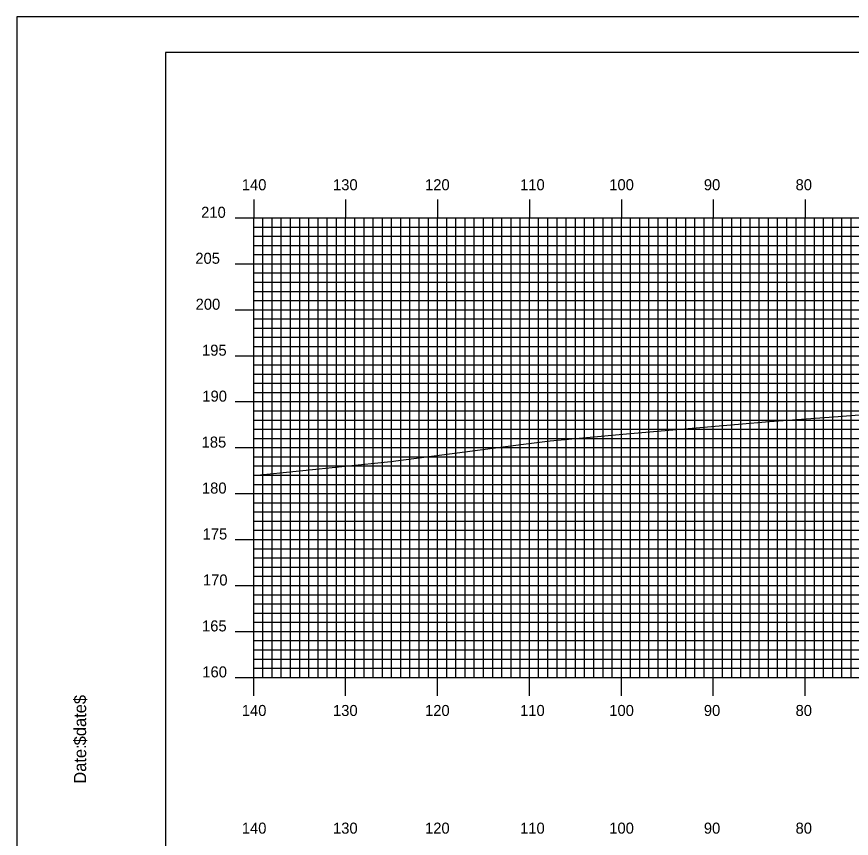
# Model space of a CAD drawing. Extents: x 1794453 to 1794796, y 442591 to 442811.
# Drawn here: x 1794452.6 to 1794543.4, y 442721.2 to 442810.5 of the extents above; entities that cross this region are included whole.
import ezdxf

# ---------------------------------------------------------------- set-up
doc = ezdxf.new("R2010")
doc.units = 0
for name, color, linetype in [('BORDER', 7, 'Continuous'), ('H_V ANNOTATION', 7, 'Continuous'), ('MAJOR', 7, 'Continuous'), ('MINOR', 7, 'Continuous'), ('PLOT BOUNDARY', 7, 'Continuous'), ('S_Roadway_Centerline', 7, 'Continuous')]:
    doc.layers.add(name, color=color, linetype=linetype)

msp = doc.modelspace()

# ---------------------------------------------------------------- linework, layer by layer
at = {"layer": 'BORDER'}
msp.add_lwpolyline([(1794468.74, 442596.665), (1794788.74, 442596.665), (1794788.74, 442806.665), (1794468.74, 442806.665)], close=True, dxfattribs=at)
at = {"layer": 'MAJOR'}
for p, q in [((1794478.34, 442790.669), (1794478.34, 442788.665)), ((1794488.34, 442790.669), (1794488.34, 442788.665)), ((1794498.34, 442790.669), (1794498.34, 442788.665)), ((1794508.34, 442790.669), (1794508.34, 442788.665)), ((1794518.34, 442790.669), (1794518.34, 442788.665)), ((1794528.34, 442790.669), (1794528.34, 442788.665)), ((1794538.34, 442790.669), (1794538.34, 442788.665)), ((1794476.336, 442788.665), (1794478.34, 442788.665)), ((1794478.34, 442788.665), (1794758.34, 442788.665)), ((1794478.34, 442738.665), (1794478.34, 442788.665)), ((1794478.34, 442738.665), (1794478.34, 442788.665)), ((1794478.34, 442788.665), (1794758.34, 442788.665)), ((1794488.34, 442738.665), (1794488.34, 442788.665)), ((1794498.34, 442738.665), (1794498.34, 442788.665)), ((1794508.34, 442738.665), (1794508.34, 442788.665)), ((1794518.34, 442738.665), (1794518.34, 442788.665)), ((1794528.34, 442738.665), (1794528.34, 442788.665)), ((1794538.34, 442738.665), (1794538.34, 442788.665)), ((1794476.336, 442783.665), (1794478.34, 442783.665)), ((1794478.34, 442783.665), (1794758.34, 442783.665)), ((1794476.336, 442778.665), (1794478.34, 442778.665)), ((1794478.34, 442778.665), (1794758.34, 442778.665)), ((1794476.336, 442773.665), (1794478.34, 442773.665)), ((1794478.34, 442773.665), (1794758.34, 442773.665)), ((1794476.336, 442768.665), (1794478.34, 442768.665)), ((1794478.34, 442768.665), (1794758.34, 442768.665)), ((1794476.336, 442763.665), (1794478.34, 442763.665)), ((1794478.34, 442763.665), (1794758.34, 442763.665)), ((1794476.336, 442758.665), (1794478.34, 442758.665)), ((1794478.34, 442758.665), (1794758.34, 442758.665)), ((1794476.336, 442753.665), (1794478.34, 442753.665)), ((1794478.34, 442753.665), (1794758.34, 442753.665)), ((1794476.336, 442748.665), (1794478.34, 442748.665)), ((1794478.34, 442748.665), (1794758.34, 442748.665)), ((1794476.336, 442743.665), (1794478.34, 442743.665)), ((1794478.34, 442743.665), (1794758.34, 442743.665)), ((1794476.336, 442738.665), (1794478.34, 442738.665)), ((1794478.34, 442738.665), (1794758.34, 442738.665)), ((1794478.34, 442738.665), (1794758.34, 442738.665)), ((1794478.34, 442736.661), (1794478.34, 442738.665)), ((1794488.34, 442736.661), (1794488.34, 442738.665)), ((1794498.34, 442736.661), (1794498.34, 442738.665)), ((1794508.34, 442736.661), (1794508.34, 442738.665)), ((1794518.34, 442736.661), (1794518.34, 442738.665)), ((1794528.34, 442736.661), (1794528.34, 442738.665)), ((1794538.34, 442736.661), (1794538.34, 442738.665))]:
    msp.add_line(p, q, dxfattribs=at)
at = {"layer": 'MINOR'}
for p, q in [((1794479.34, 442738.665), (1794479.34, 442788.665)), ((1794480.34, 442738.665), (1794480.34, 442788.665)), ((1794481.34, 442738.665), (1794481.34, 442788.665)), ((1794482.34, 442738.665), (1794482.34, 442788.665)), ((1794483.34, 442738.665), (1794483.34, 442788.665)), ((1794484.34, 442738.665), (1794484.34, 442788.665)), ((1794485.34, 442738.665), (1794485.34, 442788.665)), ((1794486.34, 442738.665), (1794486.34, 442788.665)), ((1794487.34, 442738.665), (1794487.34, 442788.665)), ((1794489.34, 442738.665), (1794489.34, 442788.665)), ((1794490.34, 442738.665), (1794490.34, 442788.665)), ((1794491.34, 442738.665), (1794491.34, 442788.665)), ((1794492.34, 442738.665), (1794492.34, 442788.665)), ((1794493.34, 442738.665), (1794493.34, 442788.665)), ((1794494.34, 442738.665), (1794494.34, 442788.665)), ((1794495.34, 442738.665), (1794495.34, 442788.665)), ((1794496.34, 442738.665), (1794496.34, 442788.665)), ((1794497.34, 442738.665), (1794497.34, 442788.665)), ((1794499.34, 442738.665), (1794499.34, 442788.665)), ((1794500.34, 442738.665), (1794500.34, 442788.665)), ((1794501.34, 442738.665), (1794501.34, 442788.665)), ((1794502.34, 442738.665), (1794502.34, 442788.665)), ((1794503.34, 442738.665), (1794503.34, 442788.665)), ((1794504.34, 442738.665), (1794504.34, 442788.665)), ((1794505.34, 442738.665), (1794505.34, 442788.665)), ((1794506.34, 442738.665), (1794506.34, 442788.665)), ((1794507.34, 442738.665), (1794507.34, 442788.665)), ((1794509.34, 442738.665), (1794509.34, 442788.665)), ((1794510.34, 442738.665), (1794510.34, 442788.665)), ((1794511.34, 442738.665), (1794511.34, 442788.665)), ((1794512.34, 442738.665), (1794512.34, 442788.665)), ((1794513.34, 442738.665), (1794513.34, 442788.665)), ((1794514.34, 442738.665), (1794514.34, 442788.665)), ((1794515.34, 442738.665), (1794515.34, 442788.665)), ((1794516.34, 442738.665), (1794516.34, 442788.665)), ((1794517.34, 442738.665), (1794517.34, 442788.665)), ((1794519.34, 442738.665), (1794519.34, 442788.665)), ((1794520.34, 442738.665), (1794520.34, 442788.665)), ((1794521.34, 442738.665), (1794521.34, 442788.665)), ((1794522.34, 442738.665), (1794522.34, 442788.665)), ((1794523.34, 442738.665), (1794523.34, 442788.665)), ((1794524.34, 442738.665), (1794524.34, 442788.665)), ((1794525.34, 442738.665), (1794525.34, 442788.665)), ((1794526.34, 442738.665), (1794526.34, 442788.665)), ((1794527.34, 442738.665), (1794527.34, 442788.665)), ((1794529.34, 442738.665), (1794529.34, 442788.665)), ((1794530.34, 442738.665), (1794530.34, 442788.665)), ((1794531.34, 442738.665), (1794531.34, 442788.665)), ((1794532.34, 442738.665), (1794532.34, 442788.665)), ((1794533.34, 442738.665), (1794533.34, 442788.665)), ((1794534.34, 442738.665), (1794534.34, 442788.665)), ((1794535.34, 442738.665), (1794535.34, 442788.665)), ((1794536.34, 442738.665), (1794536.34, 442788.665)), ((1794537.34, 442738.665), (1794537.34, 442788.665)), ((1794539.34, 442738.665), (1794539.34, 442788.665)), ((1794540.34, 442738.665), (1794540.34, 442788.665)), ((1794541.34, 442738.665), (1794541.34, 442788.665)), ((1794542.34, 442738.665), (1794542.34, 442788.665)), ((1794543.34, 442738.665), (1794543.34, 442788.665)), ((1794478.34, 442787.665), (1794758.34, 442787.665)), ((1794478.34, 442787.665), (1794480.344, 442787.665)), ((1794478.34, 442786.665), (1794758.34, 442786.665)), ((1794478.34, 442786.665), (1794480.344, 442786.665)), ((1794478.34, 442785.665), (1794758.34, 442785.665)), ((1794478.34, 442785.665), (1794480.344, 442785.665)), ((1794478.34, 442784.665), (1794758.34, 442784.665)), ((1794478.34, 442784.665), (1794480.344, 442784.665)), ((1794478.34, 442782.665), (1794758.34, 442782.665)), ((1794478.34, 442782.665), (1794480.344, 442782.665)), ((1794478.34, 442781.665), (1794758.34, 442781.665)), ((1794478.34, 442781.665), (1794480.344, 442781.665)), ((1794478.34, 442780.665), (1794758.34, 442780.665)), ((1794478.34, 442780.665), (1794480.344, 442780.665)), ((1794478.34, 442779.665), (1794758.34, 442779.665)), ((1794478.34, 442779.665), (1794480.344, 442779.665)), ((1794478.34, 442777.665), (1794758.34, 442777.665)), ((1794478.34, 442777.665), (1794480.344, 442777.665)), ((1794478.34, 442776.665), (1794758.34, 442776.665)), ((1794478.34, 442776.665), (1794480.344, 442776.665)), ((1794478.34, 442775.665), (1794758.34, 442775.665)), ((1794478.34, 442775.665), (1794480.344, 442775.665)), ((1794478.34, 442774.665), (1794758.34, 442774.665)), ((1794478.34, 442774.665), (1794480.344, 442774.665)), ((1794478.34, 442772.665), (1794758.34, 442772.665)), ((1794478.34, 442772.665), (1794480.344, 442772.665)), ((1794478.34, 442771.665), (1794758.34, 442771.665)), ((1794478.34, 442771.665), (1794480.344, 442771.665)), ((1794478.34, 442770.665), (1794758.34, 442770.665)), ((1794478.34, 442770.665), (1794480.344, 442770.665)), ((1794478.34, 442769.665), (1794758.34, 442769.665)), ((1794478.34, 442769.665), (1794480.344, 442769.665)), ((1794478.34, 442767.665), (1794758.34, 442767.665)), ((1794478.34, 442767.665), (1794480.344, 442767.665)), ((1794478.34, 442766.665), (1794758.34, 442766.665)), ((1794478.34, 442766.665), (1794480.344, 442766.665)), ((1794478.34, 442765.665), (1794758.34, 442765.665)), ((1794478.34, 442765.665), (1794480.344, 442765.665)), ((1794478.34, 442764.665), (1794758.34, 442764.665)), ((1794478.34, 442764.665), (1794480.344, 442764.665)), ((1794478.34, 442762.665), (1794758.34, 442762.665)), ((1794478.34, 442762.665), (1794480.344, 442762.665)), ((1794478.34, 442761.665), (1794758.34, 442761.665)), ((1794478.34, 442761.665), (1794480.344, 442761.665)), ((1794478.34, 442760.665), (1794758.34, 442760.665)), ((1794478.34, 442760.665), (1794480.344, 442760.665)), ((1794478.34, 442759.665), (1794758.34, 442759.665)), ((1794478.34, 442759.665), (1794480.344, 442759.665)), ((1794478.34, 442757.665), (1794758.34, 442757.665)), ((1794478.34, 442757.665), (1794480.344, 442757.665)), ((1794478.34, 442756.665), (1794758.34, 442756.665)), ((1794478.34, 442756.665), (1794480.344, 442756.665)), ((1794478.34, 442755.665), (1794758.34, 442755.665)), ((1794478.34, 442755.665), (1794480.344, 442755.665)), ((1794478.34, 442754.665), (1794758.34, 442754.665)), ((1794478.34, 442754.665), (1794480.344, 442754.665)), ((1794478.34, 442752.665), (1794758.34, 442752.665)), ((1794478.34, 442752.665), (1794480.344, 442752.665)), ((1794478.34, 442751.665), (1794758.34, 442751.665)), ((1794478.34, 442751.665), (1794480.344, 442751.665)), ((1794478.34, 442750.665), (1794758.34, 442750.665)), ((1794478.34, 442750.665), (1794480.344, 442750.665)), ((1794478.34, 442749.665), (1794758.34, 442749.665)), ((1794478.34, 442749.665), (1794480.344, 442749.665)), ((1794478.34, 442747.665), (1794758.34, 442747.665)), ((1794478.34, 442747.665), (1794480.344, 442747.665)), ((1794478.34, 442746.665), (1794758.34, 442746.665)), ((1794478.34, 442746.665), (1794480.344, 442746.665)), ((1794478.34, 442745.665), (1794758.34, 442745.665)), ((1794478.34, 442745.665), (1794480.344, 442745.665)), ((1794478.34, 442744.665), (1794758.34, 442744.665)), ((1794478.34, 442744.665), (1794480.344, 442744.665)), ((1794478.34, 442742.665), (1794758.34, 442742.665)), ((1794478.34, 442742.665), (1794480.344, 442742.665)), ((1794478.34, 442741.665), (1794758.34, 442741.665)), ((1794478.34, 442741.665), (1794480.344, 442741.665)), ((1794478.34, 442740.665), (1794758.34, 442740.665)), ((1794478.34, 442740.665), (1794480.344, 442740.665)), ((1794478.34, 442739.665), (1794758.34, 442739.665)), ((1794478.34, 442739.665), (1794480.344, 442739.665))]:
    msp.add_line(p, q, dxfattribs=at)
at = {"layer": 'PLOT BOUNDARY'}
msp.add_lwpolyline([(1794452.553, 442590.547), (1794792.553, 442590.547), (1794792.553, 442810.547), (1794452.553, 442810.547)], close=True, dxfattribs=at)
at = {"layer": 'S_Roadway_Centerline'}
msp.add_lwpolyline([(1794478.34, 442760.644), (1794493.257, 442762.151), (1794507.704, 442764.048), (1794510.595, 442764.391), (1794518.909, 442765.166), (1794531.099, 442766.231), (1794534.466, 442766.515), (1794541.925, 442767.038), (1794547.45, 442767.482)], dxfattribs=at)

# ---------------------------------------------------------------- texts
at = {"layer": 'BORDER'}
for s, p in [('$date$', (1794460.11, 442731.275)), ('Date:', (1794460.11, 442727.099))]:
    msp.add_text(s, height=1.3392, rotation=90, dxfattribs=at).set_placement(p)
at = {"layer": 'H_V ANNOTATION'}
for s, p in [('140', (1794477.045, 442791.665)), ('130', (1794486.97, 442791.665)), ('120', (1794496.98, 442791.665)), ('110', (1794507.323, 442791.665)), ('100', (1794517.023, 442791.665)), ('90', (1794527.312, 442791.665)), ('80', (1794537.291, 442791.665)), ('210', (1794472.621, 442788.665)), ('205', (1794471.989, 442783.665)), ('200', (1794472.021, 442778.665)), ('195', (1794472.717, 442773.665)), ('190', (1794472.75, 442768.665)), ('185', (1794472.674, 442763.665)), ('180', (1794472.707, 442758.665)), ('175', (1794472.781, 442753.665)), ('170', (1794472.813, 442748.665)), ('165', (1794472.717, 442743.665)), ('160', (1794472.75, 442738.665)), ('140', (1794477.045, 442734.465)), ('130', (1794486.97, 442734.465)), ('120', (1794496.98, 442734.465)), ('110', (1794507.323, 442734.465)), ('100', (1794517.023, 442734.465)), ('90', (1794527.312, 442734.465)), ('80', (1794537.291, 442734.465)), ('140', (1794477.045, 442721.665)), ('130', (1794486.97, 442721.665)), ('120', (1794496.98, 442721.665)), ('110', (1794507.323, 442721.665)), ('100', (1794517.023, 442721.665)), ('90', (1794527.312, 442721.665)), ('80', (1794537.291, 442721.665))]:
    msp.add_text(s, height=1.2, dxfattribs=at).set_placement(p)
at = {"layer": 'MAJOR'}
msp.add_text('-', height=0.012, dxfattribs=at).set_placement((1794478.331, 442738.665))

doc.saveas('drawing.dxf')
